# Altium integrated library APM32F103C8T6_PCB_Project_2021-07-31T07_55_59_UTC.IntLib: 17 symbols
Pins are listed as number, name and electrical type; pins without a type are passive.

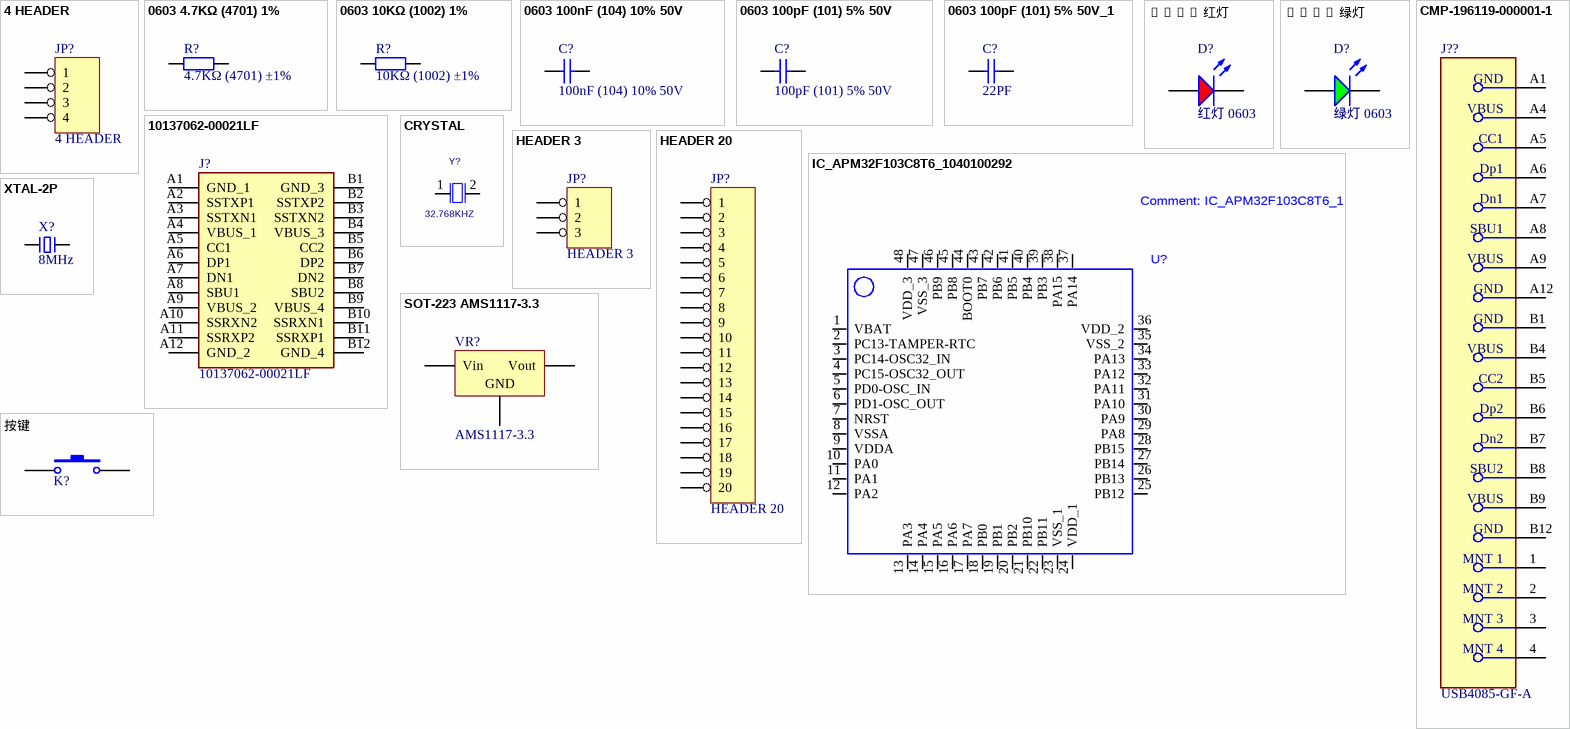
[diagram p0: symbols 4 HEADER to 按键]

## 4 HEADER
designator JP?
4 Pin Header
footprint HDR1X4 (Connector; Header; 4 Position)
pins: 1, 2, 3, 4

## 0603 4.7KΩ (4701) 1%
designator R?, comment 4.7KΩ (4701) ±1%
贴片电阻
footprint 0603_R
pins: 1, 2

## 0603 10KΩ (1002) 1%
designator R?, comment 10KΩ (1002) ±1%
贴片电阻
footprint 0603_R
pins: 1, 2

## 0603 100nF (104) 10% 50V
designator C?, comment 100nF (104) 10% 50V
贴片电容
footprint 0603_C
pins: 1, 2

## 0603 100pF (101) 5% 50V
designator C?, comment 100pF (101) 5% 50V
贴片电容
footprint 0603_C
pins: 1, 2

## 0603 100pF (101) 5% 50V_1
designator C?, comment 22PF
贴片电容
footprint 0603_C
pins: 1, 2

## 0603 红灯
designator D?, comment 红灯 0603
发光二极管
footprint 0603_LED_S1
pins: A, K

## 0603 绿灯
designator D?, comment 绿灯 0603
发光二极管
footprint 0603_LED_S1
pins: A, K

## 10137062-00021LF
designator J?
Connector; Manufacturer_Name: Amphenol
footprint 1013706200021LF
pins: A1 GND_1, A2 SSTXP1, A3 SSTXN1, A4 VBUS_1, A5 CC1, A6 DP1, A7 DN1, A8 SBU1, A9 VBUS_2, A10 SSRXN2, A11 SSRXP2, A12 GND_2, B1 GND_3, B2 SSTXP2, B3 SSTXN2, B4 VBUS_3, B5 CC2, B6 DP2, B7 DN2, B8 SBU2, B9 VBUS_4, B10 SSRXN1, B11 SSRXP1, B12 GND_4

## CMP-196119-000001-1
designator J??, comment USB4085-GF-A
CONN RCPT USB2.0 TYPEC 16POS; Manufacturer: Global Connector Technology; Description: USB - C (Type - C) USB 2.0 Receptacle Connector 16 Position Through Hole, Right Angle; Voltage Rating: 20V; Conn Orientation: Right Angle; Shielding: true; Current Rating: 4.25A; Number Of Contacts: 16; Pitch: 0.85mm; Is Female: yes
footprint FP-USB4085-GF-A-MFG
pins: 1 MNT 1, 2 MNT 2, 3 MNT 3, 4 MNT 4, A1 GND (power), A4 VBUS (power), A5 CC1, A6 Dp1, A7 Dn1, A8 SBU1, A9 VBUS (power), A12 GND (power), B1 GND (power), B4 VBUS (power), B5 CC2, B6 Dp2, B7 Dn2, B8 SBU2, B9 VBUS (power), B12 GND (power)

## CRYSTAL
designator Y?  value 32.768KHZ  (hidden comment: CRYSTAL)
XTAL 32.768KHZ 7PF 20PPM -- SMT; PCB DECAL: 3215; CAD_APPROVED: Yes; MFG_PN01: FC-135 32.7680KA-AG3; MFG_NAME01: EPSON ELECTRONICS; AGILE_PN: 230-78102; Source_Path: Q:\ORCADCIS\SYMBOLS\FCL_XTAL_OSC.OLB; CLASS: IC
footprint 3215
pins: 1, 2

## HEADER 3
designator JP?
footprint HDR1X3 (Connector; Header; 3 Position)
pins: 1, 2, 3

## HEADER 20
designator JP?
footprint HDR1X20 (Connector; Header; 20 Position)
pins: 1, 2, 3, 4, 5, 6, 7, 8, 9, 10, 11, 12, 13, 14, 15, 16, 17, 18, 19, 20

## IC_APM32F103C8T6_1040100292
designator U?
footprint LQFP48
pins: 1 VBAT, 2 PC13-TAMPER-RTC, 3 PC14-OSC32_IN, 4 PC15-OSC32_OUT, 5 PD0-OSC_IN, 6 PD1-OSC_OUT, 7 NRST, 8 VSSA, 9 VDDA, 10 PA0, 11 PA1, 12 PA2, 13 PA3, 14 PA4, 15 PA5, 16 PA6, 17 PA7, 18 PB0, 19 PB1, 20 PB2, 21 PB10, 22 PB11, 23 VSS_1, 24 VDD_1, 25 PB12, 26 PB13, 27 PB14, 28 PB15, 29 PA8, 30 PA9, 31 PA10, 32 PA11, 33 PA12, 34 PA13, 35 VSS_2, 36 VDD_2, 37 PA14, 38 PA15, 39 PB3, 40 PB4, 41 PB5, 42 PB6, 43 PB7, 44 BOOT0, 45 PB8, 46 PB9, 47 VSS_3, 48 VDD_3

## SOT-223 AMS1117-3.3
designator VR?, comment AMS1117-3.3
低压差线性稳压(LDO)
footprint SOT-223
pins: 1 GND, 2 Vout, 3 Vin

## XTAL-2P
designator X?, comment 8MHz
2脚无源脚晶振; 版权归属: 源创客
footprint OSC HC-49S
pins: 1, 2

## 按键
designator K?, comment button  (value not drawn)
Switch
footprint button_4p
pins: 1, 2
